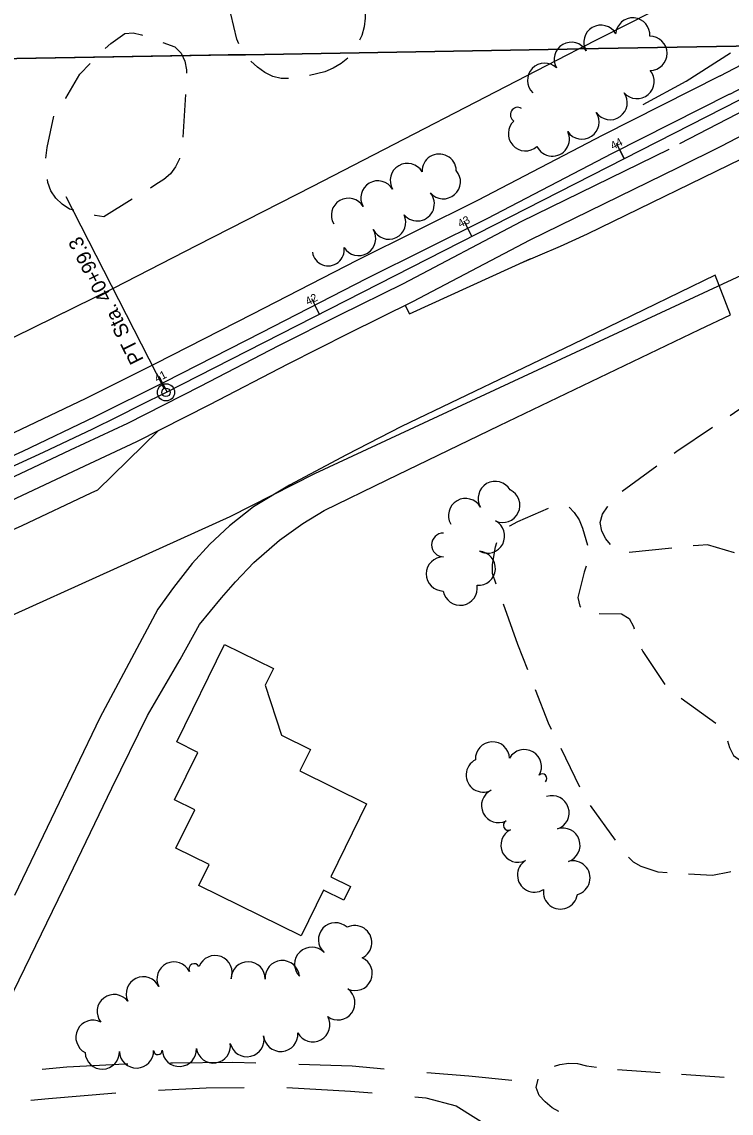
# Model space of a CAD drawing. Extents: x -2233 to 187241, y 4582 to 150524.
# Drawn here: x 104136 to 104550, y 58194 to 58832 of the extents above; entities that cross this region are included whole.
import ezdxf

# ---------------------------------------------------------------- set-up
doc = ezdxf.new("R2010")
doc.units = 0
for name, color, linetype in [('BLDG', 7, 'Continuous'), ('DRIVWY', 7, 'Continuous'), ('DV_X_Corp_Line', 7, 'Continuous'), ('GE_X_CL_100', 7, 'Continuous'), ('GE_X_CL_20', 7, 'Continuous'), ('GE_X_CL_2000', 7, 'Continuous'), ('GE_X_CL_50', 7, 'Continuous'), ('PM_X_CL_Double_Solid', 7, 'Continuous'), ('PM_X_Lane_Line', 7, 'Continuous'), ('PV_X_Shoulder', 7, 'Continuous'), ('RD_X_GR_Lt', 7, 'Continuous'), ('ROAD', 7, 'Continuous'), ('RW_X_Fee_RW', 7, 'Continuous'), ('TREES', 7, 'Continuous')]:
    doc.layers.add(name, color=color, linetype=linetype)

msp = doc.modelspace()

# ---------------------------------------------------------------- linework, layer by layer
at = {"layer": 'BLDG'}
for p, q in [((104231.44, 58788.99), (104229.94, 58764.03)), ((104161.36, 58786.63), (104161.53, 58786.85)), ((104518.72, 58580.5), (104539.47, 58594.46)), ((104517, 58579.26), (104518.72, 58580.5)), ((104486.65, 58557.23), (104506.89, 58571.91)), ((104515.68, 58523.81), (104490.81, 58521.2)), ((104425.78, 58467.47), (104417.3, 58490.99)), ((104431.56, 58452.63), (104425.78, 58467.47)), ((104521.15, 58436.12), (104541.38, 58421.42)), ((104462, 58384.16), (104450.99, 58406.61)), ((104482.85, 58353.1), (104468.14, 58373.32)), ((104484.06, 58219.13), (104508.99, 58217.27)), ((104521.46, 58216.32), (104546.39, 58214.46))]:
    msp.add_line(p, q, dxfattribs=at)
for points in [[(104262.63, 58818.71), (104261.44, 58821.37), (104257.98, 58836.24), (104258.8, 58841.36), (104259.26, 58842.92)], [(104333.77, 58844.6), (104336.62, 58838.73), (104336.53, 58833.62), (104335.85, 58828.58), (104334.53, 58823.54), (104333.22, 58820.77)], [(104184.65, 58816.01), (104187.91, 58818.78), (104195.99, 58824.69), (104201.02, 58825.17), (104205.86, 58823.84), (104206.46, 58823.63)], [(104218.25, 58819.45), (104225.21, 58816.98), (104228.92, 58813.2), (104231.12, 58808.55), (104232.04, 58803.45), (104232.02, 58801.46)], [(104161.53, 58786.85), (104169.74, 58800.9), (104175.85, 58807.13)], [(104291.66, 58798.49), (104287.5, 58798.45), (104282.52, 58799.63), (104277.97, 58801.81), (104273.54, 58804.94), (104269.62, 58808.43), (104269.62, 58808.43)], [(104326.46, 58810.29), (104322.4, 58807.08), (104317.74, 58804.37), (104312.87, 58802.38), (104303.97, 58800.14)], [(104149.98, 58751.75), (104150.58, 58758.1), (104154.6, 58776.28)], [(104228.04, 58751.76), (104227.94, 58751.44), (104225.69, 58746.67), (104222.71, 58742.62), (104218.78, 58739.26), (104214.27, 58736.34), (104211.02, 58734.33)], [(104166.22, 58721.4), (104163.67, 58722.03), (104159.47, 58724.86), (104155.77, 58728.35), (104152.85, 58732.72), (104151.07, 58737.66), (104150.82, 58739.36)], [(104200.4, 58727.76), (104183.87, 58717.55), (104178.69, 58718.36), (104178.37, 58718.44)], [(104549.84, 58601.43), (104558.04, 58606.95), (104572.28, 58612.01)], [(104421.02, 58536.71), (104421.13, 58536.8), (104425.79, 58539.43), (104443.65, 58547.28)], [(104455.7, 58547.79), (104458.62, 58544.58), (104461.54, 58540.43), (104463.53, 58535.49), (104466.39, 58525.65)], [(104479.78, 58526), (104477.13, 58529.29), (104474.78, 58533.73), (104473.8, 58538.75), (104475.11, 58543.66), (104478.09, 58548.01), (104478.25, 58548.25)], [(104413.06, 58502.75), (104410.83, 58508.92), (104410.92, 58514.24), (104412.62, 58524.55), (104413.47, 58527.07)], [(104552.39, 58521.16), (104536.54, 58525.85), (104531.21, 58525.43), (104528.11, 58525.1)], [(104465.69, 58513.31), (104464.51, 58509.81), (104460.7, 58495.01), (104461.97, 58489.92), (104462.45, 58489.3)], [(104473.21, 58485.68), (104486.27, 58485.41), (104490.76, 58482.65), (104493.25, 58477.99), (104493.63, 58476.65)], [(104498.04, 58464.98), (104498.72, 58463.37), (104511.65, 58444.05)], [(104445.49, 58417.83), (104443.65, 58421.58), (104436.09, 58440.99)], [(104548.27, 58411.12), (104549.44, 58407.3), (104551.72, 58402.64), (104555.77, 58399.65), (104561.02, 58399.57), (104566.55, 58399.45)], [(104513, 58334.03), (104507.69, 58334.34), (104497.87, 58337.69), (104493.39, 58340.31), (104490.48, 58343.22)], [(104550.25, 58334.61), (104549.5, 58334.46), (104539.52, 58332.5), (104525.48, 58333.31)], [(104447.08, 58220.92), (104450.22, 58221.93), (104455.46, 58222.78), (104460.57, 58222.46), (104465.77, 58221.22), (104471.63, 58220.37)], [(104449.76, 58194.55), (104445.79, 58196.7), (104441.72, 58200.12), (104438.16, 58203.82), (104436.46, 58208.55), (104437.55, 58213.43)]]:
    msp.add_lwpolyline(points, dxfattribs=at)
msp.add_lwpolyline([(104282.87, 58453.45), (104278.05, 58443.63), (104287.56, 58414.49), (104304.47, 58406.18), (104298.28, 58393.58), (104337.37, 58374.36), (104316.41, 58331.71), (104328.02, 58326), (104324.1, 58318.02), (104312.23, 58323.84), (104299.14, 58297.19), (104239.31, 58326.6), (104245.34, 58338.88), (104225.84, 58348.47), (104236.88, 58370.93), (104225.13, 58376.69), (104238.78, 58404.45), (104226.41, 58410.54), (104254.39, 58467.44)], close=True, dxfattribs=at)
at = {"layer": 'DRIVWY'}
for points in [[(104197.73, 58222.2), (104196.53, 58222.17), (104162.14, 58220.46), (104147.83, 58219.12)], [(104272.71, 58222.79), (104259.13, 58223.22), (104223.86, 58222.8), (104222.72, 58222.77)], [(104347.6, 58219.25), (104328.88, 58220.95), (104297.69, 58222)], [(104422.31, 58212.66), (104397.17, 58215.15), (104372.51, 58217.09)], [(104215.81, 58206.97), (104243.51, 58208.31), (104265.78, 58208.56)], [(104290.76, 58208.48), (104327.88, 58206.33), (104340.66, 58205.32)], [(104141.04, 58201.18), (104151.52, 58202.01), (104190.86, 58205.34)], [(104365.57, 58203.15), (104372.04, 58202.52), (104389.72, 58197.73), (104411.03, 58184.31)]]:
    msp.add_lwpolyline(points, dxfattribs=at)
at = {"layer": 'DV_X_Corp_Line'}
for p, q in [((104780.1, 58821.18), (104461.34, 58815.68)), ((104780.1, 58821.18), (104461.34, 58815.68)), ((104461.34, 58815.68), (104780.1, 58821.18)), ((104461.34, 58815.68), (104780.1, 58821.18)), ((104454.49, 58815.57), (104266.65, 58812.32)), ((104454.49, 58815.57), (104266.65, 58812.32)), ((104266.65, 58812.32), (104454.49, 58815.57)), ((104266.65, 58812.32), (104454.49, 58815.57)), ((104461.34, 58815.68), (104454.49, 58815.57)), ((104461.34, 58815.68), (104454.49, 58815.57)), ((104454.49, 58815.57), (104461.34, 58815.68)), ((104454.49, 58815.57), (104461.34, 58815.68)), ((104256.43, 58812.15), (104024.93, 58808.15)), ((104256.43, 58812.15), (104024.93, 58808.15)), ((104024.93, 58808.15), (104256.43, 58812.15)), ((104024.93, 58808.15), (104256.43, 58812.15)), ((104266.65, 58812.32), (104256.43, 58812.15)), ((104266.65, 58812.32), (104256.43, 58812.15)), ((104256.43, 58812.15), (104266.65, 58812.32)), ((104256.43, 58812.15), (104266.65, 58812.32))]:
    msp.add_line(p, q, dxfattribs=at)
at = {"layer": 'GE_X_CL_100'}
for p, q in [((104487.95, 58751.59), (104483.41, 58760.49)), ((104218.97, 58617.15), (104161.79, 58729.23)), ((104398.88, 58706.14), (104394.33, 58715.05)), ((104309.8, 58660.69), (104305.26, 58669.6)), ((104220.73, 58615.24), (104216.18, 58624.15))]:
    msp.add_line(p, q, dxfattribs=at)
msp.add_circle((104220.11, 58614.92), 5, dxfattribs=at)
at = {"layer": 'GE_X_CL_20'}
msp.add_line((104220.11, 58614.92), (104618.9, 58818.4), dxfattribs=at)
msp.add_arc((103178.49, 60656.39), 2291.85, 271.61534, 297.032, dxfattribs=at)
at = {"layer": 'GE_X_CL_2000'}
msp.add_line((104220.11, 58614.92), (104618.9, 58818.4), dxfattribs=at)
msp.add_arc((103178.49, 60656.39), 2291.85, 271.61534, 297.032, dxfattribs=at)
at = {"layer": 'GE_X_CL_50'}
for p, q in [((104487.95, 58751.59), (104485.68, 58756.04)), ((104398.88, 58706.14), (104396.61, 58710.59)), ((104309.8, 58660.69), (104307.53, 58665.14)), ((104220.73, 58615.24), (104218.45, 58619.69))]:
    msp.add_line(p, q, dxfattribs=at)
msp.add_circle((104220.11, 58614.92), 2.5, dxfattribs=at)
at = {"layer": 'PM_X_CL_Double_Solid'}
msp.add_line((104549.57, 58789.3), (104616.03, 58824.03), dxfattribs=at)
msp.add_lwpolyline([(104549.42, 58789.22), (104480.85, 58754.57), (104407.51, 58716.42), (104337.15, 58681.31), (104276.07, 58649.94), (104219.28, 58620.77), (104178.58, 58600.57), (104136.35, 58580.42), (104102.59, 58565.09), (104079.21, 58555.12), (104051.85, 58544.04), (104025.19, 58532.98), (103999.79, 58522.66), (103971.91, 58512.06), (103939.63, 58500.76), (103905.19, 58488.63), (103884.96, 58482.2), (103852.73, 58471.7), (103814.55, 58460.25), (103765.15, 58446.32), (103735.68, 58438.77), (103691.58, 58428.35), (103639.75, 58417.15), (103591.14, 58407.41)], dxfattribs=at)
at = {"layer": 'PM_X_Lane_Line'}
msp.add_line((104520.3, 58760.36), (104621.63, 58813.06), dxfattribs=at)
msp.add_lwpolyline([(104124.31, 58562.4), (104164.25, 58581.24), (104197.83, 58596.9), (104240.2, 58618.5), (104286.13, 58642.36), (104321.69, 58660.17), (104358.81, 58678.62), (104427.59, 58714.87), (104514.14, 58757.16), (104514.14, 58757.16)], dxfattribs=at)
at = {"layer": 'PV_X_Shoulder'}
for p, q in [((104466.47, 58707.54), (104563.94, 58755.2)), ((104450.68, 58700.34), (104466.47, 58707.54)), ((104426.92, 58690.26), (104450.68, 58700.34)), ((104362.44, 58660.77), (104433.29, 58693.17)), ((104359.88, 58665.62), (104362.44, 58660.77)), ((104180.1, 58557.76), (104215.62, 58592.5))]:
    msp.add_line(p, q, dxfattribs=at)
msp.add_lwpolyline([(104180.06, 58557.72), (104176.14, 58555.89), (104135.96, 58536.93), (104104.63, 58523.04), (104072.8, 58509.56), (104046.82, 58498.7), (104016.03, 58486.91), (103990.58, 58476.67), (103964.3, 58467.16), (103938.69, 58458.1), (103912.27, 58448.83), (103884.06, 58439.92), (103857.42, 58431.43), (103838.26, 58425.63), (103803.27, 58415.57), (103797.1, 58413.93)], dxfattribs=at)
at = {"layer": 'RD_X_GR_Lt'}
for p, q in [((104524.17, 58796.89), (104550.06, 58813.36)), ((104498.9, 58783.11), (104524.17, 58796.89))]:
    msp.add_line(p, q, dxfattribs=at)
at = {"layer": 'ROAD'}
for points in [[(104544.01, 58799.93), (104573.34, 58815.26), (104716.84, 58890.25), (104999.7, 59034.53)], [(104544.85, 58759.12), (104733.61, 58857.76), (105000.06, 58993.66)], [(104544.01, 58799.93), (104475.38, 58765.25), (104402.06, 58727.11), (104331.73, 58692.02), (104270.58, 58660.61), (104213.87, 58631.49), (104173.33, 58611.36), (104131.28, 58591.3), (104097.76, 58576.07), (104074.6, 58566.2), (104047.3, 58555.14), (104020.63, 58544.08), (103995.4, 58533.83), (103967.79, 58523.33), (103935.66, 58512.08), (103901.38, 58500.01), (103881.29, 58493.63), (103849.15, 58483.16), (103811.19, 58471.78), (103762.03, 58457.91), (103732.81, 58450.42), (103688.94, 58440.06), (103637.3, 58428.9), (103588.89, 58419.2)], [(104129.3, 58551.48), (104169.35, 58570.37), (104203.09, 58586.11), (104245.69, 58607.83), (104291.59, 58631.67), (104327.04, 58649.43), (104364.28, 58667.94), (104433.02, 58704.17), (104519.46, 58746.41), (104544.85, 58759.12)], [(104349.33, 58563.8), (104414.94, 58595.54), (104531.98, 58651.74), (104550.04, 58660.2), (104541.1, 58683.5), (104457.73, 58642.88), (104357.73, 58595.04), (104325.65, 58578.46), (104292.22, 58560.58), (104271.19, 58547.98), (104257.19, 58536.84), (104245.78, 58526.15), (104235.38, 58514.89), (104224.59, 58500.89), (104215.43, 58488.06), (104181.5, 58424.69), (104153.09, 58365.47), (104131.64, 58320.85)], [(104046.33, 58192.55), (104069.4, 58196.3), (104078.92, 58200.64), (104091.84, 58211.85), (104103.26, 58221.82), (104110.94, 58230.97), (104115.77, 58236.98), (104127.94, 58258.12), (104163.49, 58331.66), (104188.53, 58383.59), (104209.34, 58426.04), (104228.45, 58458.76), (104239.7, 58479.24), (104252.49, 58494.69), (104260.68, 58504.13), (104271.43, 58515.53), (104286.42, 58528.48), (104299.99, 58538.33), (104312.45, 58545.8), (104349.33, 58563.8)]]:
    msp.add_lwpolyline(points, dxfattribs=at)
at = {"layer": 'RW_X_Fee_RW'}
for p, q in [((102806.64, 58787.13), (104461.34, 58815.68)), ((104307, 58567.53), (104577.4, 58693.15)), ((104257.56, 58542.29), (104307, 58567.53))]:
    msp.add_line(p, q, dxfattribs=at)
for points in [[(104454.56, 58812.22), (104461.34, 58815.68), (104543.58, 58857.65)], [(104189.36, 58675.9), (104238.35, 58700.9), (104305.91, 58735.38), (104454.56, 58812.22)], [(104013.67, 58595.65), (104073, 58620.7), (104117.11, 58640.85), (104131.58, 58647.46), (104189.36, 58675.9)], [(103624.02, 58325.11), (103841.73, 58377.42), (104053.54, 58450.04), (104257.56, 58542.29)]]:
    msp.add_lwpolyline(points, dxfattribs=at)
at = {"layer": 'TREES'}
for centre, radius, start, end in [((104492.89, 58823.86), 10, 355.72998, 175.72998), ((104474.27, 58819.59), 10, 30.0814, 210.0814), ((104456.96, 58809.57), 10, 30.08841, 210.08841), ((104502.92, 58813.12), 10, 270.30213, 90.30213), ((104441.39, 58797.33), 10, 46.22245, 226.22245), ((104495.4, 58796.59), 10, 220.75576, 40.75576), ((104479.66, 58784.28), 10, 215.31111, 35.31111), ((104425.67, 58777.23), 4.32, 59.19916, 239.19916), ((104463.2, 58772.92), 10, 213.88892, 33.88892), ((104430.16, 58766.1), 10, 132.12939, 312.12939), ((104445.88, 58763.02), 10, 205.66804, 25.66804), ((104379.78, 58744.23), 10, 2.1322, 182.1322), ((104361.18, 58738.77), 10, 30.58038, 210.58038), ((104382.2, 58738.07), 10, 220.77431, 40.77431), ((104343.96, 58728.59), 10, 30.58038, 210.58038), ((104366.96, 58725.12), 10, 219.89255, 39.89255), ((104326.74, 58718.42), 10, 30.58038, 210.58038), ((104350.26, 58714.4), 10, 205.53674, 25.53674), ((104332.71, 58704.87), 10, 211.46488, 31.46488), ((104314.91, 58698.23), 9.37, 188.70493, 8.70493), ((104412.5, 58552.87), 10, 29.95461, 209.95461), ((104416.93, 58548.81), 10, 244.93009, 64.93009), ((104395.17, 58542.89), 10, 29.95461, 209.95461), ((104408.02, 58530.91), 10, 242.18937, 62.18937), ((104382.31, 58525.72), 6.95, 89.69388, 269.69388), ((104402.62, 58512.09), 10, 265.76444, 85.76444), ((104382.22, 58508.77), 10, 89.69388, 269.69388), ((104392.02, 58500.44), 10, 189.63333, 9.63333), ((104410.91, 58400.59), 10, 2.79249, 182.79249), ((104429.55, 58396.07), 10, 329.90764, 149.90764), ((104405.51, 58391.22), 10, 117.28104, 297.28104), ((104440.09, 58389.17), 2.67, 315.00707, 135.00707), ((104414.49, 58373.35), 10, 116.07721, 296.07721), ((104445.73, 58369.12), 10, 288.51147, 108.51147), ((104420.16, 58361.77), 2.89, 116.07721, 296.07721), ((104452.08, 58350.16), 10, 288.51147, 108.51147), ((104425.82, 58350.19), 10, 116.07721, 296.07721), ((104435.49, 58332.71), 10, 121.8125, 301.8125), ((104457.91, 58331.03), 10, 285.38694, 105.38694), ((104450.66, 58322.8), 10, 171.90204, 351.90204), ((104319.2, 58294.84), 10, 47.57045, 227.57045), ((104330.38, 58293.25), 10, 296.25762, 116.25762), ((104305.26, 58280.52), 10, 43.94033, 223.94033), ((104248.78, 58275.68), 10, 339.18892, 159.18892), ((104330.64, 58275.19), 10, 245.40097, 65.40097), ((104224.84, 58271.95), 10, 26.34698, 206.34698), ((104236.57, 58277.78), 3.1, 26.79249, 206.79249), ((104268.13, 58272.02), 10, 359.41513, 179.41513), ((104288.09, 58272.75), 10, 4.76907, 184.76907), ((104206.82, 58263.26), 10, 25.14681, 205.14681), ((104320.57, 58258.03), 10, 233.83687, 53.83687), ((104189.86, 58252.89), 10, 37.72466, 217.72466), ((104177.43, 58237.86), 10, 63.09034, 243.09034), ((104305.89, 58245.17), 10, 208.61477, 28.61477), ((104267.43, 58236.53), 10, 192.76996, 12.76996), ((104287.15, 58239.56), 10, 184.67938, 4.67938), ((104247.79, 58232.8), 10, 188.75244, 8.75244), ((104182.9, 58229.24), 10, 181.75113, 1.75113), ((104202.89, 58229.86), 10, 181.75113, 1.75113), ((104215.41, 58230.24), 2.53, 181.75113, 1.75113), ((104227.92, 58230.8), 10, 182.76699, 2.76699)]:
    msp.add_arc(centre, radius, start, end, dxfattribs=at)

# ---------------------------------------------------------------- texts
at = {"layer": 'GE_X_CL_100'}
msp.add_text('PT Sta. 40+99.3', height=8.42, rotation=117.032, dxfattribs=at).set_placement((104207.25, 58634))
at = {"layer": 'GE_X_CL_50'}
for s, p in [('44', (104481.28, 58756.6)), ('43', (104392.07, 58711.09)), ('42', (104303.01, 58665.65)), ('41', (104214.79, 58620.63))]:
    msp.add_text(s, height=4.68, rotation=27.032, dxfattribs=at).set_placement(p)

doc.saveas('drawing.dxf')
